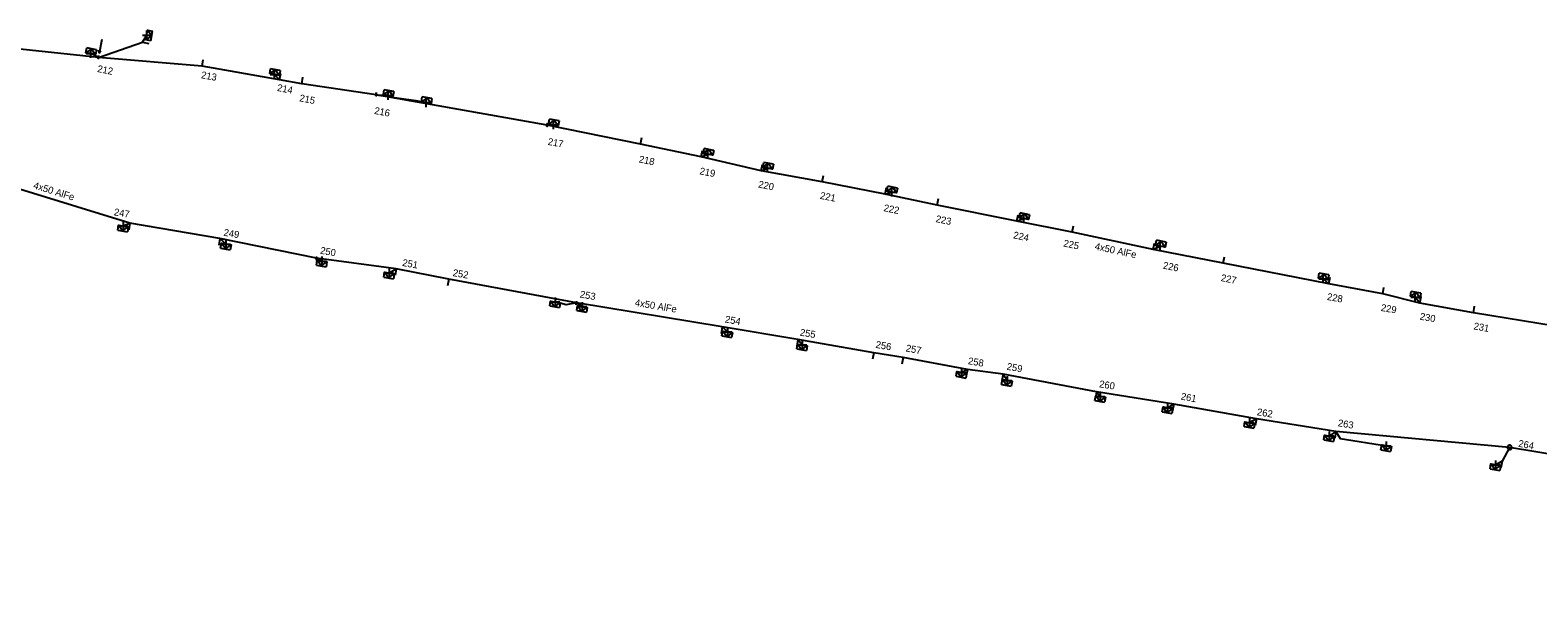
# Model space of a CAD drawing. Extents: x -544780 to -541582, y -1198995 to -1196551.
# Drawn here: x -542328.7 to -542113.7, y -1198675.3 to -1198593.1 of the extents above; entities that cross this region are included whole.
import ezdxf

# ---------------------------------------------------------------- set-up
doc = ezdxf.new("R2010")
doc.units = 0
for name, color, linetype in [('Vrstva 1', 7, 'Continuous'), ('Vrstva 13', 7, 'Continuous'), ('Vrstva 14', 7, 'Continuous'), ('Vrstva 2', 7, 'Continuous'), ('Vrstva 31', 7, 'Continuous'), ('Vrstva 34', 7, 'Continuous'), ('Vrstva 54', 7, 'Continuous'), ('Vrstva 8', 7, 'Continuous'), ('Vrstva 9', 7, 'Continuous')]:
    doc.layers.add(name, color=color, linetype=linetype)

# ---------------------------------------------------------------- blocks, each defined once
blk = doc.blocks.new('NN440')
at = {"layer": 'Vrstva 2'}
for points in [[(0.63, 0), (0.63, 0.06), (0.62, 0.13), (0.6, 0.19), (0.58, 0.25), (0.55, 0.31), (0.51, 0.37), (0.47, 0.42), (0.42, 0.46), (0.37, 0.51), (0.32, 0.54), (0.26, 0.57), (0.2, 0.59), (0.13, 0.61), (0.07, 0.62), (0, 0.63), (-0.06, 0.62), (-0.13, 0.61), (-0.19, 0.59), (-0.26, 0.57), (-0.31, 0.54), (-0.37, 0.51), (-0.42, 0.46), (-0.47, 0.42), (-0.51, 0.37), (-0.54, 0.31), (-0.57, 0.25), (-0.6, 0.19), (-0.62, 0.13), (-0.63, 0.06), (-0.63, 0), (-0.63, -0.07), (-0.62, -0.14), (-0.6, -0.2), (-0.57, -0.26), (-0.54, -0.32), (-0.51, -0.37), (-0.47, -0.43), (-0.42, -0.47), (-0.37, -0.51), (-0.31, -0.55), (-0.26, -0.58), (-0.19, -0.6), (-0.13, -0.62), (-0.06, -0.63), (0, -0.63), (0.07, -0.63), (0.13, -0.62), (0.2, -0.6), (0.26, -0.58), (0.32, -0.55), (0.37, -0.51), (0.42, -0.47), (0.47, -0.43), (0.51, -0.37), (0.55, -0.32), (0.58, -0.26), (0.6, -0.2), (0.62, -0.14), (0.63, -0.07), (0.63, 0)], [(-0.63, 0), (0.63, 0)], [(-0.6, -0.18), (0.57, -0.18)], [(-0.51, -0.32), (0.5, -0.32)], [(-0.37, -0.47), (0.35, -0.47)]]:
    blk.add_lwpolyline(points, dxfattribs=at)
blk = doc.blocks.new('NN560')
at = {"layer": 'Vrstva 2'}
for points in [[(2, 0), (1.59, 0.14)], [(0, 0), (2, 0)], [(2, 0), (1.59, -0.13)]]:
    blk.add_lwpolyline(points, dxfattribs=at)
blk = doc.blocks.new('NN800')
at = {"layer": 'Vrstva 1'}
for points in [[(-0.44, 0.44), (0.44, -0.44)], [(-0.44, -0.44), (0.44, 0.44)]]:
    blk.add_lwpolyline(points, dxfattribs=at)
blk = doc.blocks.new('NN630')
at = {"layer": 'Vrstva 9'}
for points in [[(0, -0.7), (-0.7, 0)], [(-0.7, -0.7), (-0.7, 0), (0.7, 0), (0.7, -0.7)], [(-0.7, -0.7), (0.7, -0.7)], [(0, -0.7), (0.7, 0)]]:
    blk.add_lwpolyline(points, dxfattribs=at)
blk = doc.blocks.new('NN500')
at = {"layer": 'Vrstva 2'}
for points in [[(0, -0.24), (0.02, -0.23), (0.05, -0.23), (0.07, -0.22), (0.09, -0.22), (0.12, -0.2), (0.14, -0.19), (0.16, -0.18), (0.17, -0.16), (0.19, -0.14), (0.2, -0.12), (0.21, -0.1), (0.22, -0.07), (0.23, -0.05), (0.23, -0.02), (0.23, 0), (0.23, 0.02), (0.23, 0.05), (0.22, 0.07), (0.21, 0.1), (0.2, 0.12), (0.19, 0.14), (0.17, 0.16), (0.16, 0.17), (0.14, 0.19), (0.12, 0.2), (0.09, 0.21), (0.07, 0.22), (0.05, 0.23), (0.02, 0.23), (0, 0.23), (-0.03, 0.23), (-0.05, 0.23), (-0.07, 0.22), (-0.1, 0.21), (-0.12, 0.2), (-0.14, 0.19), (-0.16, 0.17), (-0.18, 0.16), (-0.19, 0.14), (-0.2, 0.12), (-0.22, 0.1), (-0.22, 0.07), (-0.23, 0.05), (-0.23, 0.02), (-0.24, 0), (-0.23, -0.02), (-0.23, -0.05), (-0.22, -0.07), (-0.22, -0.1), (-0.2, -0.12), (-0.19, -0.14), (-0.18, -0.16), (-0.16, -0.18), (-0.14, -0.19), (-0.12, -0.2), (-0.1, -0.22), (-0.07, -0.22), (-0.05, -0.23), (-0.03, -0.23), (0, -0.24)], [(0, -0.24), (0.02, -0.23), (0.05, -0.23), (0.07, -0.22), (0.09, -0.22), (0.12, -0.2), (0.14, -0.19), (0.16, -0.18), (0.17, -0.16), (0.19, -0.14), (0.2, -0.12), (0.21, -0.1), (0.22, -0.07), (0.23, -0.05), (0.23, -0.02), (0.23, 0), (0.23, 0.02), (0.23, 0.05), (0.22, 0.07), (0.21, 0.1), (0.2, 0.12), (0.19, 0.14), (0.17, 0.16), (0.16, 0.17), (0.14, 0.19), (0.12, 0.2), (0.09, 0.21), (0.07, 0.22), (0.05, 0.23), (0.02, 0.23), (0, 0.23), (-0.03, 0.23), (-0.05, 0.23), (-0.07, 0.22), (-0.1, 0.21), (-0.12, 0.2), (-0.14, 0.19), (-0.16, 0.17), (-0.18, 0.16), (-0.19, 0.14), (-0.2, 0.12), (-0.22, 0.1), (-0.22, 0.07), (-0.23, 0.05), (-0.23, 0.02), (-0.24, 0), (-0.23, -0.02), (-0.23, -0.05), (-0.22, -0.07), (-0.22, -0.1), (-0.2, -0.12), (-0.19, -0.14), (-0.18, -0.16), (-0.16, -0.18), (-0.14, -0.19), (-0.12, -0.2), (-0.1, -0.22), (-0.07, -0.22), (-0.05, -0.23), (-0.03, -0.23), (0, -0.24)], [(0, -0.21), (0.02, -0.2), (0.04, -0.2), (0.06, -0.2), (0.08, -0.19), (0.1, -0.18), (0.12, -0.17), (0.14, -0.15), (0.15, -0.14), (0.16, -0.12), (0.18, -0.1), (0.19, -0.08), (0.19, -0.06), (0.2, -0.04), (0.2, -0.02), (0.2, 0), (0.2, 0.02), (0.2, 0.04), (0.19, 0.06), (0.19, 0.08), (0.18, 0.1), (0.16, 0.12), (0.15, 0.14), (0.14, 0.15), (0.12, 0.17), (0.1, 0.18), (0.08, 0.19), (0.06, 0.19), (0.04, 0.2), (0.02, 0.2), (0, 0.2), (-0.02, 0.2), (-0.04, 0.2), (-0.06, 0.19), (-0.08, 0.19), (-0.1, 0.18), (-0.12, 0.17), (-0.14, 0.15), (-0.15, 0.14), (-0.17, 0.12), (-0.18, 0.1), (-0.19, 0.08), (-0.2, 0.06), (-0.2, 0.04), (-0.21, 0.02), (-0.21, 0), (-0.21, -0.02), (-0.2, -0.04), (-0.2, -0.06), (-0.19, -0.08), (-0.18, -0.1), (-0.17, -0.12), (-0.15, -0.14), (-0.14, -0.15), (-0.12, -0.17), (-0.1, -0.18), (-0.08, -0.19), (-0.06, -0.2), (-0.04, -0.2), (-0.02, -0.2), (0, -0.21)], [(0, -0.18), (0.02, -0.18), (0.04, -0.17), (0.05, -0.17), (0.07, -0.16), (0.09, -0.15), (0.1, -0.14), (0.12, -0.13), (0.13, -0.12), (0.14, -0.1), (0.15, -0.09), (0.16, -0.07), (0.17, -0.05), (0.17, -0.04), (0.17, -0.02), (0.17, 0), (0.17, 0.02), (0.17, 0.04), (0.17, 0.05), (0.16, 0.07), (0.15, 0.09), (0.14, 0.1), (0.13, 0.12), (0.12, 0.13), (0.1, 0.14), (0.09, 0.15), (0.07, 0.16), (0.05, 0.17), (0.04, 0.17), (0.02, 0.17), (0, 0.18), (-0.02, 0.17), (-0.04, 0.17), (-0.06, 0.17), (-0.07, 0.16), (-0.09, 0.15), (-0.1, 0.14), (-0.12, 0.13), (-0.13, 0.12), (-0.14, 0.1), (-0.15, 0.09), (-0.16, 0.07), (-0.17, 0.05), (-0.17, 0.04), (-0.18, 0.02), (-0.18, 0), (-0.18, -0.02), (-0.17, -0.04), (-0.17, -0.05), (-0.16, -0.07), (-0.15, -0.09), (-0.14, -0.1), (-0.13, -0.12), (-0.12, -0.13), (-0.1, -0.14), (-0.09, -0.15), (-0.07, -0.16), (-0.06, -0.17), (-0.04, -0.17), (-0.02, -0.18), (0, -0.18)], [(0, -0.15), (0.01, -0.15), (0.03, -0.14), (0.04, -0.14), (0.06, -0.13), (0.07, -0.13), (0.08, -0.12), (0.1, -0.11), (0.11, -0.1), (0.12, -0.09), (0.13, -0.07), (0.13, -0.06), (0.14, -0.05), (0.14, -0.03), (0.14, -0.02), (0.14, 0), (0.14, 0.01), (0.14, 0.03), (0.14, 0.04), (0.13, 0.06), (0.13, 0.07), (0.12, 0.09), (0.11, 0.1), (0.1, 0.11), (0.08, 0.12), (0.07, 0.13), (0.06, 0.13), (0.04, 0.14), (0.03, 0.14), (0.01, 0.14), (0, 0.15), (-0.02, 0.14), (-0.03, 0.14), (-0.05, 0.14), (-0.06, 0.13), (-0.07, 0.13), (-0.09, 0.12), (-0.1, 0.11), (-0.11, 0.1), (-0.12, 0.09), (-0.13, 0.07), (-0.13, 0.06), (-0.14, 0.04), (-0.14, 0.03), (-0.15, 0.01), (-0.15, 0), (-0.15, -0.02), (-0.14, -0.03), (-0.14, -0.05), (-0.13, -0.06), (-0.13, -0.07), (-0.12, -0.09), (-0.11, -0.1), (-0.1, -0.11), (-0.09, -0.12), (-0.07, -0.13), (-0.06, -0.13), (-0.05, -0.14), (-0.03, -0.14), (-0.02, -0.15), (0, -0.15)], [(0, -0.12), (0.01, -0.12), (0.02, -0.11), (0.03, -0.11), (0.05, -0.11), (0.06, -0.1), (0.07, -0.09), (0.08, -0.09), (0.09, -0.08), (0.09, -0.07), (0.1, -0.06), (0.11, -0.05), (0.11, -0.04), (0.11, -0.02), (0.11, -0.01), (0.12, 0), (0.11, 0.01), (0.11, 0.02), (0.11, 0.04), (0.11, 0.05), (0.1, 0.06), (0.09, 0.07), (0.09, 0.08), (0.08, 0.09), (0.07, 0.09), (0.06, 0.1), (0.05, 0.11), (0.03, 0.11), (0.02, 0.11), (0.01, 0.12), (0, 0.12), (-0.01, 0.12), (-0.03, 0.11), (-0.04, 0.11), (-0.05, 0.11), (-0.06, 0.1), (-0.07, 0.09), (-0.08, 0.09), (-0.09, 0.08), (-0.1, 0.07), (-0.1, 0.06), (-0.11, 0.05), (-0.11, 0.04), (-0.12, 0.02), (-0.12, 0.01), (-0.12, 0), (-0.12, -0.01), (-0.12, -0.02), (-0.11, -0.04), (-0.11, -0.05), (-0.1, -0.06), (-0.1, -0.07), (-0.09, -0.08), (-0.08, -0.09), (-0.07, -0.09), (-0.06, -0.1), (-0.05, -0.11), (-0.04, -0.11), (-0.03, -0.11), (-0.01, -0.12), (0, -0.12)], [(0, -0.09), (0.01, -0.09), (0.02, -0.09), (0.03, -0.08), (0.03, -0.08), (0.04, -0.08), (0.05, -0.07), (0.06, -0.07), (0.06, -0.06), (0.07, -0.05), (0.07, -0.04), (0.08, -0.04), (0.08, -0.03), (0.08, -0.02), (0.09, -0.01), (0.09, 0), (0.09, 0.01), (0.08, 0.02), (0.08, 0.03), (0.08, 0.03), (0.07, 0.04), (0.07, 0.05), (0.06, 0.06), (0.06, 0.06), (0.05, 0.07), (0.04, 0.07), (0.03, 0.08), (0.03, 0.08), (0.02, 0.08), (0.01, 0.09), (0, 0.09), (-0.01, 0.09), (-0.02, 0.08), (-0.03, 0.08), (-0.04, 0.08), (-0.04, 0.07), (-0.05, 0.07), (-0.06, 0.06), (-0.07, 0.06), (-0.07, 0.05), (-0.08, 0.04), (-0.08, 0.03), (-0.08, 0.03), (-0.09, 0.02), (-0.09, 0.01), (-0.09, 0), (-0.09, -0.01), (-0.09, -0.02), (-0.08, -0.03), (-0.08, -0.04), (-0.08, -0.04), (-0.07, -0.05), (-0.07, -0.06), (-0.06, -0.07), (-0.05, -0.07), (-0.04, -0.08), (-0.04, -0.08), (-0.03, -0.08), (-0.02, -0.09), (-0.01, -0.09), (0, -0.09)], [(0, -0.06), (0, -0.06), (0.01, -0.06), (0.02, -0.05), (0.02, -0.05), (0.03, -0.05), (0.03, -0.05), (0.04, -0.04), (0.04, -0.04), (0.05, -0.03), (0.05, -0.03), (0.05, -0.02), (0.05, -0.02), (0.05, -0.01), (0.06, -0.01), (0.06, 0), (0.06, 0.01), (0.05, 0.01), (0.05, 0.02), (0.05, 0.02), (0.05, 0.03), (0.05, 0.03), (0.04, 0.04), (0.04, 0.04), (0.03, 0.05), (0.03, 0.05), (0.02, 0.05), (0.02, 0.05), (0.01, 0.06), (0, 0.06), (0, 0.06), (-0.01, 0.06), (-0.01, 0.06), (-0.02, 0.05), (-0.02, 0.05), (-0.03, 0.05), (-0.03, 0.05), (-0.04, 0.04), (-0.04, 0.04), (-0.05, 0.03), (-0.05, 0.03), (-0.05, 0.02), (-0.06, 0.02), (-0.06, 0.01), (-0.06, 0.01), (-0.06, 0), (-0.06, -0.01), (-0.06, -0.01), (-0.06, -0.02), (-0.05, -0.02), (-0.05, -0.03), (-0.05, -0.03), (-0.04, -0.04), (-0.04, -0.04), (-0.03, -0.05), (-0.03, -0.05), (-0.02, -0.05), (-0.02, -0.05), (-0.01, -0.06), (-0.01, -0.06), (0, -0.06)], [(0, -0.03), (0, -0.03), (0, -0.03), (0.01, -0.03), (0.01, -0.03), (0.01, -0.02), (0.02, -0.02), (0.02, -0.02), (0.02, -0.02), (0.02, -0.02), (0.02, -0.01), (0.02, -0.01), (0.03, -0.01), (0.03, -0.01), (0.03, 0), (0.03, 0), (0.03, 0), (0.03, 0.01), (0.03, 0.01), (0.02, 0.01), (0.02, 0.01), (0.02, 0.02), (0.02, 0.02), (0.02, 0.02), (0.02, 0.02), (0.01, 0.02), (0.01, 0.02), (0.01, 0.03), (0, 0.03), (0, 0.03), (0, 0.03), (0, 0.03), (-0.01, 0.03), (-0.01, 0.03), (-0.01, 0.02), (-0.02, 0.02), (-0.02, 0.02), (-0.02, 0.02), (-0.02, 0.02), (-0.02, 0.02), (-0.03, 0.01), (-0.03, 0.01), (-0.03, 0.01), (-0.03, 0.01), (-0.03, 0), (-0.03, 0), (-0.03, 0), (-0.03, -0.01), (-0.03, -0.01), (-0.03, -0.01), (-0.03, -0.01), (-0.02, -0.02), (-0.02, -0.02), (-0.02, -0.02), (-0.02, -0.02), (-0.02, -0.02), (-0.01, -0.03), (-0.01, -0.03), (-0.01, -0.03), (0, -0.03), (0, -0.03)], [(0.23, 0), (0.7, 0)]]:
    blk.add_lwpolyline(points, dxfattribs=at)
blk = doc.blocks.new('NN510')
at = {"layer": 'Vrstva 2'}
blk.add_lwpolyline([(0, 0), (0, 0.94)], dxfattribs=at)

msp = doc.modelspace()

# ---------------------------------------------------------------- linework, layer by layer
at = {"layer": 'Vrstva 1'}
for points in [[(-542111.23, -1198635.28), (-542122.88, -1198633.37), (-542130.5, -1198631.99), (-542135.81, -1198630.68), (-542143.48, -1198629.24), (-542158.56, -1198626.31), (-542168.55, -1198624.37), (-542180.12, -1198621.89), (-542187.99, -1198620.33), (-542199.36, -1198618.02), (-542206.79, -1198616.46), (-542215.75, -1198614.71), (-542224.49, -1198613.14), (-542233.04, -1198611.15), (-542241.7, -1198609.33), (-542255.01, -1198606.65), (-542279.39, -1198602.29), (-542290, -1198600.73), (-542293.19, -1198600.17), (-542304.21, -1198598.23), (-542319.01, -1198596.98), (-542348.55, -1198593.85)], [(-542039.71, -1198675.3), (-542040.53, -1198674.87), (-542063.64, -1198662.97), (-542087.39, -1198657.56), (-542117.71, -1198652.57), (-542142.48, -1198650.32), (-542153.84, -1198648.51), (-542165.61, -1198646.39), (-542176.66, -1198644.65), (-542189.96, -1198642.15), (-542195.05, -1198641.46), (-542204.23, -1198639.77), (-542208.42, -1198639.08), (-542219.22, -1198637.21), (-542230.02, -1198635.4), (-542250.83, -1198631.96), (-542269.04, -1198628.6), (-542276.53, -1198627.1), (-542287.9, -1198625.6), (-542301.67, -1198622.79), (-542314.54, -1198620.61), (-542337.89, -1198613.42)]]:
    msp.add_lwpolyline(points, dxfattribs=at)
at = {"layer": 'Vrstva 54'}
for points in [[(-542319.01, -1198596.98), (-542312.72, -1198594.81), (-542312.12, -1198593.78)], [(-542319.01, -1198596.98), (-542320.11, -1198596.43)], [(-542293.19, -1198600.17), (-542293.88, -1198599.41)], [(-542279.39, -1198602.29), (-542277.68, -1198602.4)], [(-542279.39, -1198602.29), (-542276.1, -1198602.76), (-542273.71, -1198603.13), (-542272.25, -1198603.42)], [(-542255.01, -1198606.65), (-542254.11, -1198606.59)], [(-542224.49, -1198613.14), (-542223.56, -1198612.76)], [(-542206.79, -1198616.46), (-542205.84, -1198616.16)], [(-542187.99, -1198620.33), (-542187.01, -1198619.95)], [(-542168.55, -1198624.37), (-542167.54, -1198623.87)], [(-542287.9, -1198625.6), (-542287.1, -1198626)], [(-542276.53, -1198627.1), (-542277.5, -1198627.71)], [(-542143.48, -1198629.24), (-542144.29, -1198628.54)], [(-542130.5, -1198631.99), (-542131.18, -1198631.15)], [(-542250.83, -1198631.96), (-542252.3, -1198632.23), (-542253.82, -1198631.83)], [(-542250.83, -1198631.96), (-542249.97, -1198632.5)], [(-542230.02, -1198635.4), (-542229.25, -1198636.1)], [(-542219.22, -1198637.21), (-542218.59, -1198637.96)], [(-542195.05, -1198641.46), (-542195.87, -1198641.87)], [(-542176.66, -1198644.65), (-542176.06, -1198645.32)], [(-542165.61, -1198646.39), (-542166.45, -1198646.93)], [(-542153.84, -1198648.51), (-542154.77, -1198649.03)], [(-542142.48, -1198650.32), (-542143.41, -1198650.94)], [(-542142.48, -1198650.32), (-542141.87, -1198651.3), (-542135.27, -1198652.33)], [(-542117.71, -1198652.57), (-542118.79, -1198654.55), (-542119.69, -1198655.04)]]:
    msp.add_lwpolyline(points, dxfattribs=at)
at = {"layer": 'Vrstva 8'}
for points in [[(-542233.04, -1198611.15), (-542232.06, -1198610.77)], [(-542314.54, -1198620.61), (-542315.45, -1198621.02)], [(-542301.67, -1198622.79), (-542300.78, -1198623.59)], [(-542189.96, -1198642.15), (-542189.35, -1198643.02)]]:
    msp.add_lwpolyline(points, dxfattribs=at)

# ---------------------------------------------------------------- block references
at = {"layer": 'Vrstva 13'}
for name, p, rotation in [('NN560', (-542318.51, -1198594.42), -101.06085837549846), ('NN510', (-542312.72, -1198594.81), -100.02534724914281), ('NN510', (-542304.21, -1198598.23), -10.027744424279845), ('NN510', (-542293.19, -1198600.17), -10.984935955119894), ('NN510', (-542290.01, -1198600.73), -10.984936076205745), ('NN510', (-542241.7, -1198609.33), -11.211991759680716), ('NN510', (-542233.04, -1198611.15), -11.211991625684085), ('NN510', (-542224.49, -1198613.14), -11.565944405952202), ('NN510', (-542215.75, -1198614.71), -11.109913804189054), ('NN510', (-542206.79, -1198616.46), -11.539297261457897), ('NN510', (-542199.36, -1198618.02), -11.539297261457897), ('NN510', (-542187.99, -1198620.33), -11.737941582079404), ('NN510', (-542314.53, -1198620.61), 170.07998594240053), ('NN510', (-542180.12, -1198621.89), -11.737941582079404), ('NN510', (-542301.67, -1198622.79), 170.14824168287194), ('NN510', (-542168.55, -1198624.37), -11.270005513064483), ('NN510', (-542158.56, -1198626.31), -11.270005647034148), ('NN510', (-542276.53, -1198627.1), 170.00541670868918), ('NN510', (-542269.04, -1198628.6), 170.00541670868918), ('NN510', (-542143.49, -1198629.24), -9.919780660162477), ('NN510', (-542135.81, -1198630.68), -9.919780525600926), ('NN510', (-542130.5, -1198631.99), -10.078288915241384), ('NN510', (-542122.88, -1198633.37), -10.078288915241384), ('NN510', (-542230.02, -1198635.4), 170.0298722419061), ('NN510', (-542219.22, -1198637.21), 170.4488749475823), ('NN510', (-542208.42, -1198639.08), 170.4488749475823), ('NN510', (-542204.23, -1198639.77), 169.9183305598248), ('NN510', (-542195.05, -1198641.46), 169.91833042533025), ('NN510', (-542189.96, -1198642.15), 169.99010830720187), ('NN510', (-542176.66, -1198644.64), 171.04668876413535), ('NN510', (-542165.61, -1198646.39), 169.3450806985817), ('NN510', (-542153.84, -1198648.5), 170.68891396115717), ('NN510', (-542142.48, -1198650.32), 170.3495027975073), ('NN510', (-542118.79, -1198654.55), 170.42747771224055)]:
    msp.add_blockref(name, p, dxfattribs=dict(at, rotation=rotation))
for name, p, xscale, yscale, rotation in [('NN500', (-542319.01, -1198596.98), 0.5, 0.5, 78.93899992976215), ('NN500', (-542279.39, -1198602.29), 0.5, 0.5000000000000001, 79.01500004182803), ('NN500', (-542255.01, -1198606.65), 0.5, 0.49999999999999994, 79.83500001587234), ('NN500', (-542287.9, -1198625.6), 0.5, 0.5, -100.13600002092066), ('NN500', (-542250.83, -1198631.96), 0.5000000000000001, 0.4999999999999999, -99.83300001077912), ('NN440', (-542117.71, -1198652.57), 0.5000000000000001, 0.5, -10.541511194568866)]:
    msp.add_blockref(name, p, dxfattribs=dict(at, xscale=xscale, yscale=yscale, rotation=rotation))
at = {"layer": 'Vrstva 31'}
for p, rotation in [((-542312.12, -1198593.78), 79.97465277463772), ((-542320.11, -1198596.43), 168.93914161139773), ((-542293.88, -1198599.41), 169.96434714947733), ((-542277.68, -1198602.4), 169.01506391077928), ((-542272.25, -1198603.42), 170.16992224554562), ((-542254.11, -1198606.59), 169.83508320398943), ((-542232.06, -1198610.77), 168.7880082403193), ((-542223.56, -1198612.76), 168.43405558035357), ((-542205.84, -1198616.16), 168.4607028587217), ((-542187.01, -1198619.95), 168.26205840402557), ((-542315.45, -1198621.02), -9.920013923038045), ((-542300.78, -1198623.59), -9.851758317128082), ((-542167.54, -1198623.87), 168.72999448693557), ((-542287.1, -1198626), -10.136002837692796), ((-542277.5, -1198627.71), -9.994583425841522), ((-542144.29, -1198628.55), 170.08021933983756), ((-542131.18, -1198631.15), 169.92171109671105), ((-542253.82, -1198631.83), -9.8069722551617), ((-542249.97, -1198632.5), -9.83308623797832), ((-542229.25, -1198636.1), -9.97012776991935), ((-542218.59, -1198637.95), -9.55112518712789), ((-542195.87, -1198641.87), -10.081669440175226), ((-542189.36, -1198643.02), -10.009891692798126), ((-542176.06, -1198645.32), -8.953311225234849), ((-542166.46, -1198646.93), -10.654919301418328), ((-542154.77, -1198649.03), -9.31108617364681), ((-542143.41, -1198650.94), -9.650497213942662), ((-542135.27, -1198652.33), -9.784874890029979), ((-542119.69, -1198655.04), -9.572522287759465)]:
    msp.add_blockref('NN630', p, dxfattribs=dict(at, rotation=rotation))
at = {"layer": 'Vrstva 34'}
for p, rotation in [((-542312.12, -1198593.78), 45), ((-542320.11, -1198596.43), 45), ((-542293.88, -1198599.41), 45), ((-542277.68, -1198602.4), 45.00000009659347), ((-542272.25, -1198603.42), 45), ((-542254.11, -1198606.59), 45), ((-542232.06, -1198610.77), 45.00000009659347), ((-542223.56, -1198612.76), 45), ((-542205.84, -1198616.16), 45), ((-542315.45, -1198621.02), 45), ((-542187.01, -1198619.95), 45), ((-542300.78, -1198623.59), 45), ((-542167.54, -1198623.87), 45), ((-542287.1, -1198626), 45), ((-542277.5, -1198627.71), 45), ((-542144.29, -1198628.55), 45), ((-542253.82, -1198631.83), 45), ((-542131.18, -1198631.15), 44.99999995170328), ((-542249.97, -1198632.5), 45), ((-542229.25, -1198636.1), 44.99999995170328), ((-542218.59, -1198637.96), 45), ((-542195.87, -1198641.87), 45), ((-542189.35, -1198643.02), 45), ((-542176.06, -1198645.32), 45.00000009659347), ((-542166.45, -1198646.93), 44.99999995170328), ((-542154.77, -1198649.03), 45), ((-542143.41, -1198650.94), 45), ((-542135.27, -1198652.33), 45), ((-542119.69, -1198655.04), 45.00000009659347)]:
    msp.add_blockref('NN800', p, dxfattribs=dict(at, rotation=rotation))

# ---------------------------------------------------------------- texts
at = {"layer": 'Vrstva 14'}
for s, rotation, p in [('212', 348.939, (-542319.22, -1198599.04)), ('213', 349.972, (-542304.42, -1198599.93)), ('214', 349.015, (-542293.58, -1198601.74)), ('215', 349.015, (-542290.4, -1198603.21)), ('216', 349.015, (-542279.72, -1198605.01)), ('217', 349.835, (-542254.97, -1198609.43)), ('218', 348.788, (-542241.98, -1198611.93)), ('219', 348.788, (-542233.32, -1198613.62)), ('220', 348.434, (-542224.95, -1198615.5)), ('221', 348.89, (-542216.14, -1198617.12)), ('222', 348.461, (-542207.07, -1198618.87)), ('247', 350.08, (-542316.85, -1198619.47)), ('223', 348.461, (-542199.64, -1198620.43)), ('249', 350.148, (-542301.21, -1198622.38)), ('224', 348.262, (-542188.58, -1198622.75)), ('250', 349.864, (-542287.44, -1198624.95)), ('225', 348.262, (-542181.43, -1198623.91)), ('251', 350.005, (-542275.72, -1198626.69)), ('226', 348.73, (-542167.22, -1198627.07)), ('252', 350.005, (-542268.52, -1198628.13)), ('227', 348.73, (-542158.96, -1198628.84)), ('253', 350.167, (-542250.38, -1198631.19)), ('228', 350.08, (-542143.81, -1198631.54)), ('229', 350.08, (-542136.13, -1198633.1)), ('230', 349.922, (-542130.58, -1198634.35)), ('254', 350.03, (-542229.69, -1198634.75)), ('231', 349.922, (-542122.91, -1198635.73)), ('255', 350.449, (-542219, -1198636.62)), ('256', 350.449, (-542208.2, -1198638.37)), ('257', 349.918, (-542203.9, -1198638.88)), ('258', 349.918, (-542195.02, -1198640.69)), ('259', 349.99, (-542189.5, -1198641.49)), ('260', 351.047, (-542176.31, -1198643.99)), ('261', 349.345, (-542164.67, -1198645.74)), ('262', 350.689, (-542153.8, -1198647.97)), ('263', 350.35, (-542142.26, -1198649.54)), ('264', 349.458, (-542116.54, -1198652.46))]:
    msp.add_text(s, height=1, rotation=rotation, dxfattribs=at).set_placement(p)
at = {"layer": 'Vrstva 2'}
for rotation, p in [(342.899, (-542328.37, -1198615.63)), (347.912, (-542176.95, -1198624.35)), (350.625, (-542242.54, -1198632.39))]:
    msp.add_text('4x50 AlFe', height=1, rotation=rotation, dxfattribs=at).set_placement(p)

doc.saveas('drawing.dxf')
